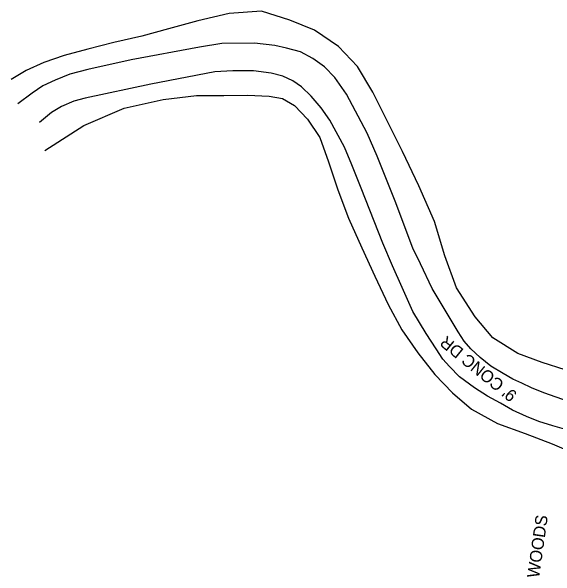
# Model space of a CAD drawing. Extents: x 1698744 to 1699848, y 707609 to 709748.
# Drawn here: x 1699032.8 to 1699212, y 708276.5 to 708462.7 of the extents above; entities that cross this region are included whole.
import ezdxf

# ---------------------------------------------------------------- set-up
doc = ezdxf.new("R2010")
doc.units = 0
for name, color, linetype in [('Exist Roads EOP Other', 7, 'Continuous'), ('Exist Roads EOP Other Text', 7, 'Continuous'), ('Exist Vegetation Woods Line', 7, 'Continuous'), ('Exist Vegetation Woods Line Text', 7, 'Continuous')]:
    doc.layers.add(name, color=color, linetype=linetype)

msp = doc.modelspace()

# ---------------------------------------------------------------- linework, layer by layer
at = {"layer": 'Exist Roads EOP Other'}
for points in [[(1699179.91, 708357.14), (1699171.29, 708371.35), (1699167.54, 708379.55), (1699165.01, 708384.7), (1699159.2, 708400.16), (1699153.21, 708414.93), (1699149.92, 708422.58), (1699143.15, 708435.38), (1699139.24, 708440.91), (1699135.85, 708444.33), (1699132, 708447.16), (1699128.02, 708449.28), (1699123.42, 708450.57), (1699119.49, 708451.44), (1699112.8, 708452.22), (1699102.08, 708452.01), (1699094.77, 708450.91), (1699072.26, 708446.72), (1699057.99, 708443.51), (1699052.03, 708441.96), (1699047.14, 708440), (1699043.16, 708438.08), (1699039.63, 708435.67), (1699034.88, 708432.2)], [(1699172.68, 708351.55), (1699169.34, 708356.58), (1699164.97, 708363.85), (1699161.44, 708371.71), (1699158.27, 708378.91), (1699155.06, 708386.35), (1699148, 708404.42), (1699144.86, 708412.08), (1699142.52, 708417.94), (1699137.67, 708426.86), (1699134.78, 708430.85), (1699131.5, 708434.71), (1699128.28, 708437.85), (1699125.51, 708439.79), (1699122.14, 708441.32), (1699118.27, 708442.32), (1699112.5, 708443.02), (1699105.7, 708443.08), (1699099.77, 708442.79), (1699078.69, 708438.7), (1699057.07, 708434.07), (1699053.33, 708433.04), (1699049.25, 708431.29), (1699045.94, 708429.32), (1699042.01, 708426.1)], [(1699208.13, 708337.02), (1699208.13, 708337.02), (1699204, 708338.75), (1699200.84, 708340.2), (1699197.91, 708341.6), (1699194.73, 708343.4), (1699190.71, 708345.84), (1699187.17, 708348.64), (1699184.04, 708351.5), (1699181.87, 708354.01), (1699179.91, 708357.14)], [(1699206.42, 708327.6), (1699206.42, 708327.6), (1699202.45, 708329.24), (1699197.83, 708331.39), (1699193.86, 708333.6), (1699189.6, 708335.97), (1699185.29, 708338.67), (1699180.38, 708342.31), (1699177.09, 708345.7), (1699174.81, 708348.14), (1699172.68, 708351.55)], [(1699224.2, 708331.56), (1699216.23, 708334.16), (1699208.13, 708337.02)], [(1699282.59, 708309.46), (1699280.88, 708311.95), (1699278.22, 708314.19), (1699275.32, 708315.24), (1699271.79, 708315.78), (1699266.56, 708316.2), (1699260.27, 708316.65), (1699252.32, 708317.46), (1699245.88, 708318.13), (1699238.29, 708319.41), (1699231.71, 708320.66), (1699221.79, 708323.09), (1699211.04, 708326.21), (1699206.42, 708327.6)]]:
    msp.add_lwpolyline(points, dxfattribs=at)
at = {"layer": 'Exist Vegetation Woods Line'}
for points in [[(1699215.11, 708344.61), (1699207.58, 708346.99), (1699199.5, 708350.03), (1699191.37, 708355.11), (1699185.46, 708362.03), (1699179.37, 708371.66), (1699175.47, 708382.14), (1699172.06, 708393.5), (1699166.99, 708405.19), (1699161.57, 708416.55), (1699156.87, 708425.99), (1699151.82, 708436.05), (1699146.7, 708444.49), (1699140.54, 708451.11), (1699132.64, 708456.47), (1699124.49, 708459.71), (1699115.15, 708462.66), (1699104.54, 708461.96), (1699094.12, 708459.54), (1699084.5, 708456.87), (1699075.74, 708454.44), (1699066.55, 708452.37), (1699057.91, 708450.19), (1699050.14, 708448.09), (1699043.5, 708445.81), (1699037.65, 708443.13), (1699032.75, 708440.17)], [(1699043.76, 708416.83), (1699056.66, 708425.05), (1699069.87, 708430.72), (1699082.74, 708433.66), (1699093.7, 708434.91), (1699102.69, 708434.98), (1699110.56, 708435.04), (1699117.65, 708434.71), (1699122.07, 708433.91), (1699126.05, 708431.65), (1699130.31, 708427.18), (1699134.31, 708421.14), (1699137.15, 708413.11), (1699140.29, 708403.89), (1699143.75, 708394.61), (1699148.2, 708384.8), (1699152.44, 708375.49), (1699156.88, 708366.11), (1699161.4, 708357.8), (1699166.65, 708350.26), (1699172.17, 708343.12), (1699178.06, 708337.09), (1699184.29, 708331.72), (1699192.89, 708326.93), (1699201.95, 708323.67), (1699210.81, 708320.31), (1699217.72, 708317.33)]]:
    msp.add_lwpolyline(points, dxfattribs=at)

# ---------------------------------------------------------------- texts
at = {"layer": 'Exist Roads EOP Other Text'}
msp.add_text("9' CONC DR", height=4, rotation=140.8956, dxfattribs=at).set_placement((1699199.62, 708336.85))
at = {"layer": 'Exist Vegetation Woods Line Text'}
msp.add_text('WOODS', height=4, rotation=81.8738, dxfattribs=at).set_placement((1699206.53, 708275.93))

doc.saveas('drawing.dxf')
